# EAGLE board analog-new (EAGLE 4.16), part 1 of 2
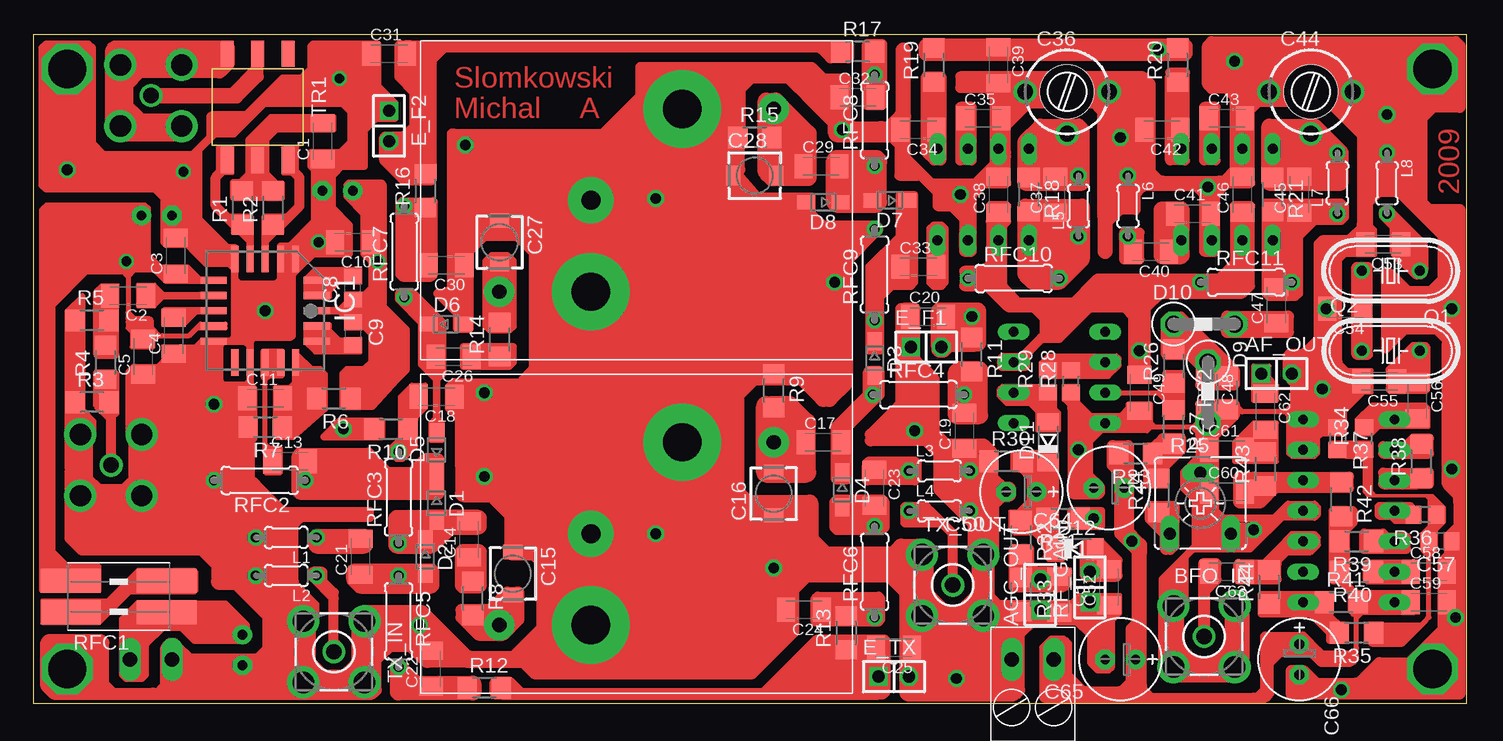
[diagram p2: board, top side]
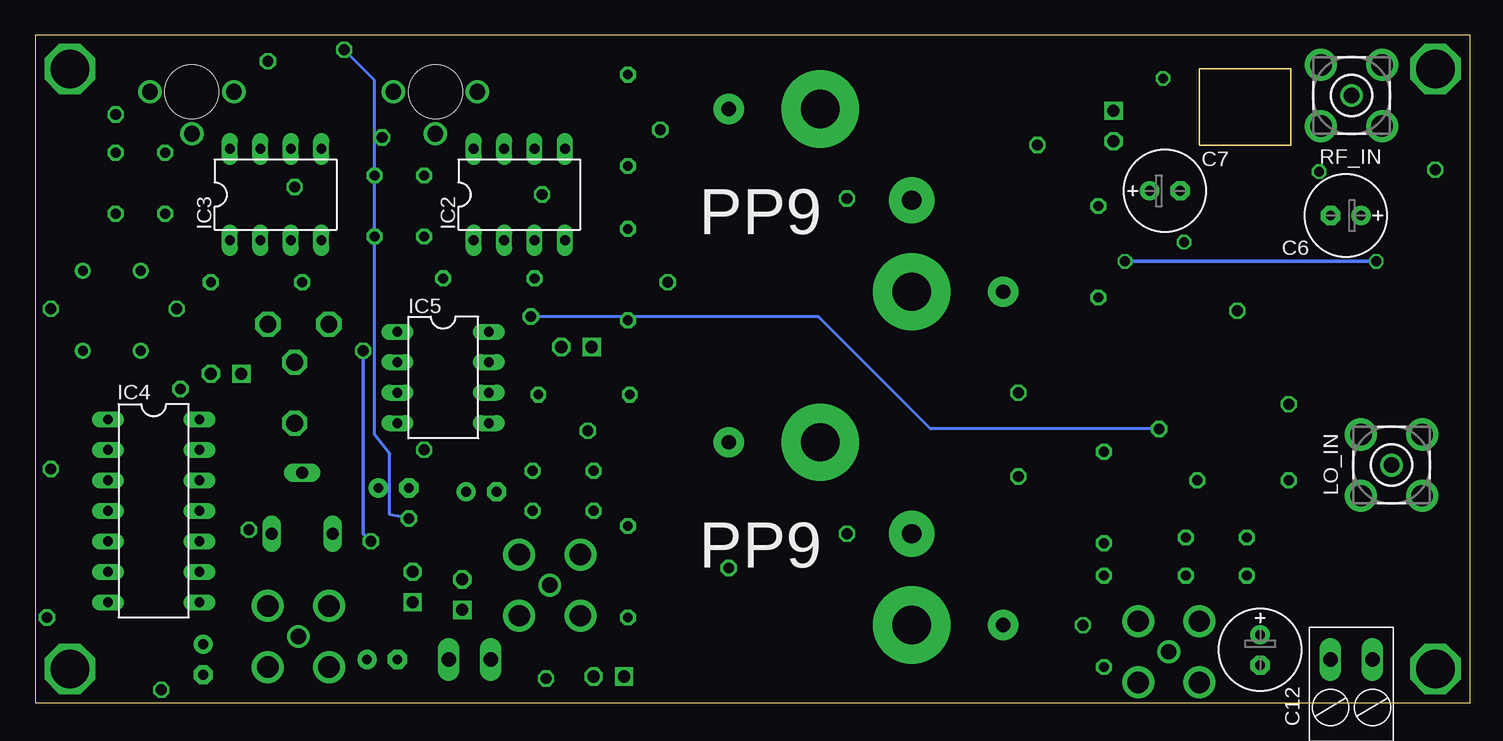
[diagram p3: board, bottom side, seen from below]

Size 119.52 x 55.71 mm. Coordinates in mm from the lower left corner, seen from the top.
Outline: 0,0 119.52,0 119.52,55.71 0,55.71 0,0
Copper layers (1*16): Top 0.035mm / dielectric 1.5mm / Bottom 0.035mm
Design rules "default": minimum track width 10mil, minimum drill 24mil, track to track 8mil, track to pad 8mil, pad to pad 8mil, via to via 8mil, smd to smd 8mil, copper to edge 40mil, drill to drill 8mil, minimum pad ring 10mil, minimum via ring 8mil, stop-mask expansion 4mil, vias tented up to drill 0mil, thermal gap 10mil

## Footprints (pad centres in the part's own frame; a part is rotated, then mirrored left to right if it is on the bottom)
RIACON-2 = drill 1.2 long: P$1 0,1.75; P$2 0,-1.75
1X02 = drill 1.016 square: 1 -1.27,0 | drill 1.016 octagon: 2 1.27,0
BU-SMA-V = drill 1.27 round: 1 0,0 | drill 1.778 round: 2 -2.55,2.55; 3 2.55,2.55; 4 2.55,-2.55; 5 -2.55,-2.55
C1206K = smd 1.5 x 2: 1 -1.5,0; 2 1.5,0
E2,5-7 = drill 0.813 pad 1.6 round: + -1.27,0 | drill 0.813 pad 1.6 octagon: - 1.27,0
C0805 = smd 1.3 x 1.5: 1 -0.95,0; 2 0.95,0
CTRIMTZBX4 = smd 1.6 x 1.2: 1 0,1.8; 2 0,-1.8
CTRIM3040.428 = drill 1.3 round: 1A -3.5,0; 1B 3.5,0; 2 0,-3.5 | hole 4.5: 0,0
SOD323-W = smd 1.5 x 1.2: A 1.45,0; C -1.45,0
C1702-05 = drill 1.397 octagon: A 2.54,0; C -2.54,0
SOD80C = smd 1.4 x 1.8: A 1.7,0; C -1.7,0
PP9 = drill 1.6 pad 3.81 round: GND 0,7.62 | drill 1.2 pad 2.54 round: IO1 7.62,0; IO2 -15.24,15.24 | drill 3.2 pad 6.452 round: P$1 0,0; P$2 -7.62,15.24
PLCC20S = smd 0.6 x 2.2: 1 0,4.3; 2 -1.27,4.3; 3 -2.54,4.3; 9 -2.54,-4.3; 10 -1.27,-4.3; 11 0,-4.3; 12 1.27,-4.3; 13 2.54,-4.3; 19 2.54,4.3; 20 1.27,4.3 | smd 2.2 x 0.6: 4 -4.3,2.54; 5 -4.3,1.27; 6 -4.3,0; 7 -4.3,-1.27; 8 -4.3,-2.54; 14 4.3,-2.54; 15 4.3,-1.27; 16 4.3,0; 17 4.3,1.27; 18 4.3,2.54
DIL08 = drill 0.813 long: 1 -3.81,-3.81; 2 -1.27,-3.81; 3 1.27,-3.81; 4 3.81,-3.81; 5 3.81,3.81; 6 1.27,3.81; 7 -1.27,3.81; 8 -3.81,3.81
DIL14 = drill 0.813 long: 1 -7.62,-3.81; 2 -5.08,-3.81; 3 -2.54,-3.81; 4 0,-3.81; 5 2.54,-3.81; 6 5.08,-3.81; 7 7.62,-3.81; 8 7.62,3.81; 9 5.08,3.81; 10 2.54,3.81; 11 0,3.81; 12 -2.54,3.81; 13 -5.08,3.81; 14 -7.62,3.81
0204/5 = drill 0.813 octagon: 1 -2.54,0; 2 2.54,0
HC49U70 = drill 0.813 round: 1 -2.413,0; 2 2.413,0
R1206 = smd 1.6 x 1.803: 1 -1.422,0; 2 1.422,0
CA6V = drill 1.016 long: A -2.54,-2.54; E 2.54,-2.54; S 0,2.54
R0805 = smd 1.3 x 1.5: 1 -0.95,0; 2 0.95,0
WE-CMS_7427521 = smd 5 x 2: 1 -4,1.3; 2 -4,-1.3; 3 4,-1.3; 4 4,1.3
0207/7 = drill 0.813 octagon: 1 -3.81,0; 2 3.81,0
MINICIRCUITS-W38 = smd 1.067 x 2.184: 1 -2.54,6.35; 2 0,6.35; 3 2.54,6.35; 4 2.54,-2.54; 5 0,-2.54; 6 -2.54,-2.54

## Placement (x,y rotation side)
+-5V  [RIACON-2]  9.84,3.64 90 bottom
+-5V1  [RIACON-2]  83.34,3.64 90 top
AF_OUT  [1X02]  103.66,27.46 0 top
AGC_OUT  [1X02]  83.97,9.04 90 top
BFO_IN  [BU-SMA-V]  97.63,5.55 0 top
C1  100n  [C1206K]  24.12,46.83 90 top
C2  100n  [C1206K]  7.93,33.97 180 top
C3  100n  [C1206K]  11.9,37.3 90 top
C4  100n  [C1206K]  11.74,30.63 90 top
C5  100n  [C1206K]  9.2,28.89 90 top
C6  100u  [E2,5-7]  10.31,40.63 180 bottom
C7  100u  [E2,5-7]  25.39,42.7 0 bottom
C8  1n  [C0805]  26.67,34.6 90 top
C9  1n  [C0805]  26.67,30.79 270 top
C10  100n  [C1206K]  26.67,38.41 180 top
C11  100n  [C1206K]  19.36,25.39 0 top
C12  100u  [E2,5-7]  17.46,4.44 270 bottom
C13  1n  [C1206K]  21.43,20.16 0 top
C14  1n  [C1206K]  36.35,13.65 90 top
C15  30p  [CTRIMTZBX4]  40,10.79 180 top
C16  30p  [CTRIMTZBX4]  61.75,17.46 0 top
C17  1n  [C1206K]  65.88,21.74 0 top
C18  100n  [C1206K]  33.65,25.55 180 top
C19  100n  [C1206K]  77.62,22.7 90 top
C20  100n  [C1206K]  74.61,32.22 0 top
C21  1n  [C1206K]  27.3,12.22 90 top
C22  100n  [C1206K]  33.17,2.85 90 top
C23  1n  [C1206K]  70.16,17.93 270 top
C24  100n  [C1206K]  64.29,7.77 180 top
C25  100n  [C1206K]  71.75,4.6 180 top
C26  1n  [C1206K]  35.08,28.89 180 top
C27  30p  [CTRIMTZBX4]  38.89,38.41 180 top
C28  30p  [CTRIMTZBX4]  60.16,43.97 270 top
C29  1n  [C1206K]  65.72,44.76 0 top
C30  100n  [C1206K]  34.44,36.51 180 top
C31  100n  [C1206K]  29.68,54.13 0 top
C32  100n  [C1206K]  68.73,50.48 0 top
C33  100p  [C1206K]  73.81,36.35 0 top
C34  10n  [C1206K]  73.81,47.78 180 top
C35  22n  [C1206K]  79.21,48.73 0 top
C36  30p  [CTRIM3040.428]  86.2,50.95 0 top
C37  100p  [C1206K]  85.24,42.38 90 top
C38  100n  [C1206K]  80.48,42.38 90 top
C39  10n  [C1206K]  80.48,53.17 270 top
C40  22n  [C1206K]  93.18,37.62 180 top
C41  100p  [C1206K]  96.67,40.79 0 top
C42  10n  [C1206K]  94.13,47.78 180 top
C43  22n  [C1206K]  99.53,48.73 0 top
C44  30p  [CTRIM3040.428]  106.52,50.95 0 top
C45  100p  [C1206K]  105.56,42.38 90 top
C46  100n  [C1206K]  100.8,42.38 90 top
C47  10p  [C1206K]  103.66,33.17 90 top
C48  10n  [C1206K]  97.94,25.87 270 top
C49  100n  [C1206K]  92.23,25.87 270 top
C50  47u  [E2,5-7]  82.39,17.61 180 top
C51  10n  [C1206K]  85.56,9.04 270 top
C52  10n  [C1206K]  89.69,9.68 90 top
C53  [C1206K]  112.55,38.25 180 top
C54  [C1206K]  109.37,32.85 180 top
C55  [C1206K]  112.23,26.82 180 top
C56  [C1206K]  115.41,25.23 270 top
C57  10n  [C0805]  117.31,13.49 180 top
C58  10n  [C1206K]  116.36,10.95 0 top
C59  100n  [C1206K]  116.36,8.41 0 top
C60  10n  [C1206K]  99.53,17.61 0 top
C61  10n  [C1206K]  99.53,21.11 0 top
C62  10n  [C1206K]  102.71,24.28 270 top
C63  10n  [C1206K]  99.53,10.95 180 top
C64  100u  [E2,5-7]  89.69,17.93 180 top
C65  100u  [E2,5-7]  90.64,3.64 180 top
C66  100u  [E2,5-7]  105.56,3.64 270 top
D1  [SOD323-W]  33.65,16.66 270 top
D2  [SOD323-W]  32.7,12.22 270 top
D3  [SOD323-W]  70.16,28.73 270 top
D4  [SOD323-W]  67.46,17.77 270 top
D5  [SOD323-W]  33.65,21.11 90 top
D6  [SOD323-W]  34.44,31.59 0 top
D7  [SOD323-W]  71.43,41.9 180 top
D8  [SOD323-W]  65.88,41.74 180 top
D9  [C1702-05]  97.94,25.87 270 top
D10  [C1702-05]  97.63,31.58 0 top
D11  [SOD80C]  84.61,21.74 90 top
D12  [SOD80C]  86.83,12.85 0 top
E_F1  [1X02]  74.45,29.68 0 top
E_F2  [1X02]  29.68,48.09 270 top
E_TX  [1X02]  71.75,2.22 0 top
F1  PP9  [PP9]  46.51,34.28 0 bottom
F2  PP9  [PP9]  46.51,6.5 0 bottom
IC1  AD831  [PLCC20S]  19.36,32.7 270 top
IC2  MC1350  [DIL08]  79.21,42.38 0 bottom
IC3  MC1350  [DIL08]  99.53,42.38 0 bottom
IC4  MC1496  [DIL14]  109.69,16.03 270 bottom
IC5  CA3130N  [DIL08]  85.56,27.14 270 bottom
L1  [0204/5]  21.11,13.8 180 top
L2  [0204/5]  21.11,10.63 180 top
L3  [0204/5]  75.56,19.36 0 top
L4  [0204/5]  75.56,16.03 0 top
L5  [0204/5]  87.15,41.43 90 top
L6  [0204/5]  91.28,41.43 270 top
L7  [0204/5]  108.74,43.33 90 top
L8  [0204/5]  112.87,43.33 270 top
LO_IN  [BU-SMA-V]  6.5,19.84 90 bottom
Q1  [HC49U70]  113.18,36.03 180 top
Q2  [HC49U70]  113.18,29.36 0 top
R1  100  [R1206]  17.46,41.27 90 top
R2  100  [R1206]  20,41.27 90 top
R3  100  [R1206]  4.92,25.08 0 top
R4  [R1206]  6.03,28.41 90 top
R5  100  [R1206]  4.92,31.9 0 top
R6  4k7  [R1206]  25.08,25.39 180 top
R7  4k7  [R1206]  19.36,23.01 180 top
R8  470  [R1206]  36.67,8.72 270 top
R9  560  [R1206]  61.75,26.03 270 top
R10  1k  [R1206]  29.84,22.85 180 top
R11  1k  [R1206]  78.26,29.04 270 top
R12  2k2  [R1206]  37.62,1.26 0 top
R13  2k2  [R1206]  67.78,5.87 90 top
R14  [R1206]  38.89,30.32 90 top
R15  [R1206]  60.16,47.14 0 top
R16  1k  [R1206]  32.7,42.7 90 top
R17  1k  [R1206]  68.73,54.29 0 top
R18  1k  [R1206]  83.02,42.38 270 top
R19  5k1  [R1206]  75.08,53.17 90 top
R20  10k  [R1206]  95.4,53.17 90 top
R21  2k2  [R1206]  103.34,42.38 270 top
R22  100k  [R1206]  99.53,25.87 90 top
R23  10k  [R1206]  91.91,20.79 180 top
R24  100  [R1206]  93.82,17.3 90 top
R25  22k  [CA6V]  97.31,16.66 0 top
R26  1M  [R1206]  95.09,28.09 90 top
R27  1M  [R1206]  95.09,23.01 270 top
R28  3k3  [R0805]  86.51,26.82 90 top
R29  10k  [R0805]  84.61,26.82 90 top
R30  47k  [R1206]  81.12,20.15 0 top
R31  220  [R1206]  85.88,15.39 180 top
R32  [R1206]  82.39,13.81 270 top
R33  [R1206]  82.39,9.04 270 top
R34  1k  [R0805]  110.96,22.06 90 top
R35  820  [R1206]  110.33,5.87 180 top
R36  1k  [R0805]  116.04,15.71 180 top
R37  1k  [R0805]  108.74,22.06 270 top
R38  100  [R1206]  115.72,20.15 90 top
R39  10k  [R1206]  110.33,13.49 180 top
R40  3k3  [R1206]  110.33,10.95 180 top
R41  1k3  [R1206]  109.06,8.41 0 top
R42  3k3  [R1206]  109.06,16.98 270 top
R43  1k  [R1206]  102.71,19.52 90 top
R44  50  [R1206]  103.02,9.68 90 top
RF_GAIN  [1X02]  88.1,9.68 90 top
RF_IN  [BU-SMA-V]  9.84,50.64 180 bottom
RFC1  [WE-CMS_7427521]  7.14,8.88 0 top
RFC2  [0207/7]  18.89,18.57 180 top
RFC3  [0207/7]  30.48,17.14 90 top
RFC4  [0207/7]  73.81,25.71 0 top
RFC5  [0207/7]  30.48,6.82 270 top
RFC6  [0207/7]  70.16,10.95 90 top
RFC7  [0207/7]  30.95,37.62 90 top
RFC8  [0207/7]  70.16,48.57 90 top
RFC9  [0207/7]  70.16,35.71 90 top
RFC10  [0207/7]  81.75,35.39 0 top
RFC11  [0207/7]  101.12,35.08 0 top
TR1  [MINICIRCUITS-W38]  18.73,51.59 180 top
TX_IN  [BU-SMA-V]  25.08,4.28 270 top
TX_OUT  [BU-SMA-V]  76.67,9.84 0 top

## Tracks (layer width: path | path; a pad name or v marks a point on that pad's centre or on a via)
C62
  Top 1.27: 102.71,21.11 C62.2 | 102.71,21.11 102.87,20.94 R43.2 | C61.2 102.71,21.11
N$1
  Top 0.61: 9.2,33.97 C2.1 IC1.10
N$2
  Top 1.422: R8.1 36.2,10.15 36.19,10.15 36.35,10.31 C14.1
N$3
  Top 0.813: R3.2 6.35,24.92 6.5,24.76 LO_IN.1
  Top 1.422: R4.1 6.34,26.67 R3.2
N$4
  Top 1.016: TR1.4 16.19,53.49 15.87,53.17 13.49,53.17 13.48,53.19 RF_IN.4
  Top 2.184: 7.3,53.17 8.24,53.19 RF_IN.5 | RF_IN.4 8.26,53.19 7.3,53.17 | RF_IN.3 8.26,48.09 7.3,48.09 | 7.3,48.09 8.24,48.09 RF_IN.2 | 7.3,48.09 7.3,53.17
N$5
  Top 0.61: IC1.20 23.66,30.3 23.81,30.16 | C9.2 25.08,29.84 24.76,30.16 23.81,30.16 | IC1.19 23.81,30.16
N$6
  Top 0.61: IC1.2 23.66,35.09 23.81,35.24 | C8.2 25.08,35.55 24.76,35.24 23.81,35.24 | 23.81,35.24 IC1.3
N$7
  Top 1.422: C2.2 6.43,31.83 6.35,31.74 6.34,31.75 R5.2 6.03,31.58 R4.2
N$8
  Top 1.422: R14.1 C26.1
N$9
  Top 1.27: 34.76,15.15 34.76,15.23 34.74,15.21 D1.A
  Top 1.422: 33.17,13.33 | 33.17,13.33 33.17,13.65 | RFC3.1 33.17,13.33 | 33.17,13.33 | 33.17,13.65 D2.C | C14.2 34.76,15.15 34.67,15.15 33.17,13.65
N$10
  Top 0.61: 8.89,8.25 16.03,8.25 17.78,6.5 17.78,5.55 17.46,5.23 13.49,5.23 12.54,6.18 | 12.54,6.18 | 12.54,6.18 12.38,6.34 10.79,6.34 9.36,4.92 9.36,2.38 9.04,2.06 7.77,2.06 | 7.46,6.03 7.46,2.38 7.77,2.06 | 7.46,6.03 7.46,6.18 | 7.77,2.06 7.93,2.06 | 7.46,6.03 7.46,6.98 8.73,8.25
N$11
  Top 0.61: R2.1 20,40.32 19.36,40.32 19.36,39.84 | IC1.6 19.36,39.84 | 19.36,39.84 19.36,40.48 21.11,40.48
  Top 0.813: TR1.1 21.27,44.76 22.22,43.81 22.22,41.43 20.63,39.84 20,40 R2.1
N$12
  Top 0.61: RFC1.3 11.14,7.49 9.36,5.71 8.09,5.71
  Top 1.27: C12.+ 14.44,5.71 12.7,7.46 11.43,7.46 11.27,7.61 11.24,7.58 RFC1.3
  Top 1.778: 11.11,7.61 RFC1.3 | +-5V.P$2 8.09,5.71
N$13
  Top 0.813: TR1.5 18.73,53.02 16.35,50.63 | RF_IN.1 16.35,50.63 | 16.35,50.63
N$14  (via drill 3.2)
  Top 0.305: v116.68,2.85 116.84,2.85 117.31,2.38 | 117.31,2.38 117.95,1.74 117.31,1.74 115.72,3.33 116.36,3.33 117.31,2.38
  Top 1.676: 117.31,2.38 116.36,1.42
N$15
  Top 1.016: 21.59,23.49 23.17,25.08
N$16
  Top 1.016: 25.71,37.94 25.71,38.89
N$17
  Top 0.406: C13.1 19.84,20.31 19.36,20.79 19.36,20.95 | 19.36,20.95 19.36,21.58 | 19.36,21.58 19.36,26.98 | 19.36,26.98 19.36,27.3 | 19.36,27.62 IC1.16 | 19.36,26.98 19.68,27.3 20.79,27.3 20.79,29.36 19.2,29.36 19.2,27.14 19.36,26.98 | 19.36,20.95 19.36,19.2 20.63,19.2 20.63,21.27 19.68,21.27 19.36,21.58
  Top 0.61: IC1.17 20.49,28.4 20.47,28.41 20.46,28.4 IC1.16 | 19.36,27.3 19.36,27.62
N$18
  Top 0.406: 6.66,23.81 6.98,24.12 6.98,27.46 6.82,27.62 5.23,27.62 5.23,26.98 | 5.23,26.98 5.23,27.14 | 5.23,26.98 5.23,24.76 6.35,23.65
N$19
  Top 0.406: 5.55,24.76 5.55,26.19
N$20
  Top 0.406: 5.39,28.89 5.23,29.04 5.23,34.28 5.71,34.76 6.98,34.76 6.98,29.04 6.82,28.89 5.39,28.89
N$21
  Top 0.406: 6.66,30.47 6.66,31.11
N$22
  Top 0.406: 5.55,32.06 5.55,34.44
N$23
  Top 1.016: 40.48,9.2 40.48,6.98 39.21,5.71 37.14,5.71 35.71,7.14 35.71,7.77 38.1,7.77 39.52,9.2 40.32,9.2
N$24
  Top 1.016: 39.84,6.98 39.84,7.93
N$25
  Top 1.422: F2.IO1 | F2.IO1 | C15.1 38.89,7.88 38.89,7.3 | 38.89,7.3 F2.IO1 | R8.2 36.36,7.3 38.89,7.3
N$26
  Top 1.676: 61.75,24.44 R9.2 | F2.IO2 61.75,24.44 | 61.75,24.44 | F2.IO2 | F2.IO2 C17.1 | F2.IO2 | 61.75,21.58 | 61.75,21.58 F2.IO2 | C16.1 61.75,21.58
N$27
  Top 1.016: 69.69,25.87 69.69,27.62 70.48,27.62 70.48,25.71 67.78,23.01 67.78,18.73 | 69.69,25.39 69.69,25.87 | 69.69,25.87 69.69,25.71 66.99,23.01 66.99,18.73 67.62,18.73
  Top 1.27: D3.A 70.16,25.87 RFC4.1 69.69,25.39 67.38,23.08 C17.2 67.46,21.74 D4.C
N$28
  Top 1.422: R11.2 78.26,26.35 RFC4.2 C19.2
N$29
  Top 1.422: C18.2 32.06,25.55 31.27,24.76 R10.1 | RFC3.2 | RFC3.2 31.27,21.74 R10.1 | R10.1
N$30
  Top 1.016: 36.98,6.34 38.89,6.34
N$31  (via drill 0.9)
  Top 1.27: R11.1 77,30.47 76.67,30.79 | 76.67,30.79 76.04,31.43 76.04,32.22 | 76.04,32.22 | 76.04,32.22 C20.2 | E_F1.2 75.72,29.84 76.67,30.79 | E_F1.2 | v78.26,32.22 E_F1.2 | R10.2 | R10.2 | v25.87,22.85 R10.2
  Bottom 0.254: v78.26,32.22 54.29,32.22 44.92,22.85 v25.87,22.85
N$32
  Top 1.422: 26.98,10.63 27.07,10.72 C21.1 | 26.98,10.63 RFC5.1 33.17,10.63 | 26.98,10.63 | 33.17,10.63 | 33.17,10.63 D2.A | 33.17,10.63 32.86,10.63
N$33  (via drill 3.2)
  other vias: 2.85,52.86
N$34
  Top 1.27: D4.A 70.14,16.32 70.16,16.34 | 70.16,16.34 | 70.16,16.34 C23.2 | RFC6.2 70.16,16.34
N$35
  Top 1.27: C24.1 67.31,7.77 R13.2 67.78,7.14 | 67.78,7.14 RFC6.1 | 67.78,7.14
N$36
  Top 1.016: R12.2 39.05,0.79 | 70.48,2.38 E_TX.1 70.48,0.79 39.05,0.79 | 39.05,0.79 38.57,0.79 38.57,1.74 39.68,1.74 40.48,0.95
  Top 1.27: 70.16,4.6 | 70.16,4.6 C25.2 70.25,4.53 70.16,4.44 70.16,4.45 R13.1 | 70.48,2.38 70.48,4.28 70.16,4.6
N$37
  Top 1.422: 30.48,2.06 RFC5.2 | RFC5.2 | 30.48,2.06 31.11,1.42 32.86,1.42 32.93,1.35 C22.1 33.26,1.35 33.33,1.42 R12.1 | RFC5.2 31.9,1.58 | 30.48,2.06 30.48,0.95 36.67,0.95 36.67,1.58 31.59,1.58
N$38
  Top 0.61: 18.09,39.2 18.09,40.16 17.62,40 | 18.09,39.2 IC1.7 | 18.09,39.2 18.09,40.48 16.51,40.48
  Top 0.813: TR1.3 16.19,44.76 15.24,43.81 15.24,41.43 16.82,39.84 17.62,40 R1.1
N$39
  Top 1.422: 27.14,13.81 27.23,13.72 C21.2 | L1.1 27.14,13.81 | 27.14,13.81
N$40
  Top 0.813: L2.1 25.08,9.2 TX_IN.1
N$41
  Top 1.27: 70.16,19.36 | C23.1 70.16,19.36 | 70.16,19.36 L3.1 | 70.16,19.36
N$42
  Top 0.813: TX_OUT.1 76.67,14.12 75.08,15.71 | 75.08,15.71 74.77,16.03 L4.1 | L4.1 | 75.08,15.71 74.45,16.34 72.7,16.34 72.7,15.08 75.56,15.08
N$43
  Top 1.422: 37.14,9.84 35.87,9.84 35.87,12.54 37.14,12.54 37.14,9.84
N$44
  Top 1.016: 33.17,18.57 33.17,18.73 33.15,18.7 33.15,18.41 | 33.15,18.41 D1.C | 33.15,18.41 33.17,18.41 | 33.65,18.88 D5.C
  Top 1.27: 33.65,18.25 | D1.C 33.65,18.25 | 33.65,18.25 33.65,18.88 | 33.65,18.25
  Top 1.422: C13.2 22.77,20.24 22.86,20.15 22.7,20 RFC2.1 33.17,18.57
N$45
  Top 0.61: 33.65,29.04 33.58,28.97 | D5.A 33.65,29.04 | 33.65,29.04
  Top 1.422: C26.2 33.58,28.97 33.65,29.04 32.99,29.7 D6.C 32.99,32.04 33.02,32.06 31.27,33.81 RFC7.1
N$46
  Top 1.676: R14.2 F1.IO1 | F1.IO1 | F1.IO1 C27.1
N$47
  Top 1.676: 70,44.76 C29.2 | 70,44.76 RFC8.1 | 70,44.76 69.98,44.74 D7.A 70,42.22 | 70,42.22 | D8.C 69.53,41.74 70,42.22
N$48
  Top 1.422: 33.02,15.39 37.14,15.39 37.14,14.76 34.76,14.76 33.17,13.17 30.32,13.17 30.32,15.39 33.49,15.39 33.65,15.23
N$49
  Top 1.676: F1.IO2 61.75,47.14 61.59,46.98 61.58,46.99 R15.2 61.91,47.14 61.96,47.09 61.96,44.76 | C28.1 61.96,44.76 | 61.96,44.76 C29.1
N$51
  Top 1.27: D7.C 72.88,38.91 70.64,36.66 | 70.64,36.66 70.16,36.19 RFC9.1 | RFC9.1 | D3.C RFC9.1 | C33.1 70.96,36.35 70.64,36.66
N$52
  Top 0.61: 29.21,43.17 29.21,33.01 31.11,31.11 31.11,27.77 30.32,26.98 28.25,24.76 25.87,24.76 25.87,27.46 26.19,27.77 27.62,27.77 28.25,28.41
N$53
  Top 1.422: C32.2 70.23,50.39 70.16,50.32 RFC8.2 R17.2
N$54
  Top 1.016: R17.1 67.31,54.6 67.31,54.76 65.88,54.76 | C31.2 31.18,54.69 31.11,54.76 31.43,54.76 | 31.43,54.76 32.7,54.76 | 32.7,54.76 65.88,54.76 | 32.7,54.76 32.7,54.6 32.7,46.82 | 32.7,46.82 R16.2 | 32.7,46.82 | 32.7,46.82 E_F2.2 | 32.7,46.82 | 31.43,54.76 30.63,54.76 30.63,52.22 31.9,50.95 31.9,48.09 30.95,47.14 29.36,47.14 29.36,45.24 30.95,43.65 33.17,43.65 33.17,53.65 33.97,54.45 | 65.88,54.76 67.94,54.76 67.94,53.81 66.51,53.81 65.72,54.6
N$55
  Top 0.813: 18.73,42.86 TR1.2 | R1.2 17.46,42.86 18.73,42.86 | R2.2 18.88,43.01 18.73,42.86
  Top 1.016: C1.2 19.91,48.32 18.73,47.14 TR1.2
N$56
  Top 1.422: 30.95,14.44 33.17,14.44
N$57
  Top 1.422: 26.82,10.95 33.17,10.95
N$58
  Top 1.422: 26.82,10.31 26.82,10.79 | 26.82,10.31 | 26.82,10.31 27.3,9.84 33.17,9.84 33.17,10.47
N$59
  Top 1.422: 27.62,13.17 23.65,13.17 23.65,13.81 27.62,13.81 27.62,13.49
N$60
  Top 0.813: 25.08,8.73 23.33,10.47 23.33,10.95 24.13,10.95 24.13,10.15
N$61
  Top 0.61: C4.2 11.74,32.38 12.06,32.7 IC1.11
N$62  (via drill 3.2)
  other vias: 116.68,52.86
N$63
  Top 0.61: 21.9,25.39 21.9,27.93 | 21.9,27.93 IC1.18 | 21.9,25.39 C11.2 20.79,25.39 20.63,25.23 20.78,25.08 R7.1 | 21.9,25.39 R6.2 | 21.9,27.93 21.9,26.66 21.43,26.19
N$64
  Top 0.406: 19.52,47.62 19.52,44.13 20.32,43.33 20.79,43.33 20.79,42.06 16.66,42.06 16.66,43.49 17.3,43.49 17.93,44.13 17.93,46.98 19.84,48.89 25.08,48.89 25.08,47.78
N$65
  Top 0.61: 25.08,5.23 25.55,4.76 | 25.08,5.23 | 24.6,4.76 25.08,5.23
N$66
  Top 0.305: 9.68,37.46 9.68,41.27 9.36,41.59 1.11,41.59 0.79,41.27 0.63,41.11 0.63,40.79 0.63,40.63 0.63,9.36
N$67
  Top 0.406: 25.08,47.78 20.32,47.78 19.36,46.82 19.36,44.13
N$68
  Top 0.406: 18.25,43.97 18.25,46.98
N$69
  Top 1.016: 19.52,43.49 18.89,44.13
N$70
  Top 1.016: 17.62,43.33 18.57,44.28
N$71
  Top 1.016: 17.93,42.38 19.36,42.38
N$73
  Top 0.305: 25.4,35.08 27.3,35.08 27.3,36.19 23.49,36.19 22.7,35.39 22.7,33.81 24.76,33.81 24.76,34.28 25.55,35.08
N$74
  Top 0.813: 26.03,35.87 23.65,35.87 23.33,35.55
N$75
  Top 0.813: 26.98,35.39 25.24,35.39 24.28,34.44
N$76
  Top 0.813: 24.44,34.92 23.17,34.92 23.17,34.44
N$77
  Top 0.305: 23.33,29.36 22.7,30 22.7,31.58 24.76,31.58 24.76,31.11 25.55,30.31 27.3,30.31 27.3,29.2 23.49,29.2 23.33,29.36 | 23.33,29.36
N$78
  Top 0.813: 26.51,29.52 23.65,29.52 23.33,29.84
N$79
  Top 0.813: 26.35,30 25.4,30 24.44,30.95
N$80
  Top 0.813: 24.13,30.47 24.13,30.95
N$81
  Top 0.813: 23.01,30.47 23.01,31.11
N$83
  Top 1.016: RFC1.4 8.44,10.18 5.87,7.61 3.17,7.61 RFC1.2
N$84
  Top 0.61: 28.25,34.6 28.25,36.82 27.62,37.46 27.62,40.79 26.19,42.22 26.19,43.17 26.35,43.33 29.05,43.33 29.21,43.17
N$85
  Top 1.676: 61.59,24.76 63.02,24.76 64.45,23.33 64.45,19.2 62.38,19.2 61.11,19.2 61.11,24.76
N$86
  Top 1.422: 26.67,25.87 27.94,27.14
N$87
  Top 1.422: 26.35,26.66 26.82,27.14
N$88
  Top 1.422: 27.14,42.7 28.73,42.7 28.73,41.59
N$89
  Top 1.422: 28.09,37.62 28.09,39.68
N$90
  Top 1.422: 28.73,31.58 28.73,33.97
N$91
  Top 1.422: 26.98,32.85 28.25,32.85
N$92
  Top 0.61: 26.35,33.49 | 26.35,33.49 25.55,32.7 26.35,31.9
N$93
  Top 0.305: 21.43,26.35 20.16,26.35 20.16,22.22 20.32,22.06 21.74,22.06 24.44,24.44 | 24.44,24.44 23.49,24.28 23.65,24.44 24.44,24.44 | 24.44,24.44 24.44,27.46 23.97,27.93 23.01,27.93 21.9,29.04
  Top 0.61: 21.9,29.04 23.17,27.77
N$94
  Top 0.813: 22.22,25.71 22.22,28.25
N$95
  Top 0.813: 22.7,25.87 22.7,27.77
N$96
  Top 0.813: 23.97,26.19 23.97,27.3
N$97
  Top 0.813: 23.65,26.19 23.65,27.62
N$98
  Top 0.813: 23.17,26.5 23.17,27.46
N$99
  Top 1.016: 23.49,25.08 23.81,24.6 21.43,22.54
N$100
  Top 1.016: 20.63,23.65 20.63,24.76
N$101
  Top 1.016: 21.11,23.81 22.38,25.08
N$102
  Top 1.016: 21.74,24.76 21.74,25.39
N$103
  Top 0.305: 13.49,11.11 13.65,10.95 13.65,9.36 13.49,9.2 8.09,9.2 5.55,6.66 0.79,6.66 0.79,6.82 0.79,8.57 6.19,8.57 8.73,11.11 13.49,11.11
N$104
  Top 1.27: 12.38,52.7 15.55,52.7 16.19,53.33 16.19,54.6 6.82,54.6 6.66,54.45 6.66,53.17 | 12.38,47.46 7.3,47.46 6.66,48.09 6.66,53.17 | 6.66,53.17 7.3,53.81
N$105
  Top 1.27: 12.85,53.97 15.55,53.97
N$106
  Top 1.016: 18.73,54.6 18.73,52.22 16.98,50.48 9.84,50.48
N$107
  Top 1.016: 16.82,50.79 9.84,50.79 9.84,50.63
N$108
  Top 0.61: 8.57,10.63 8.89,10.63
N$109
  Top 0.61: 8.25,9.52 8.89,9.52
N$110
  Top 0.61: 5.87,8.25 5.55,8.25
N$111
  Top 0.61: 5.71,7.14 5.55,7.14
N$112
  Top 0.305: 0.79,9.36 5.55,9.36 5.55,11.42 5.39,11.58 2.85,11.58 1.74,12.69
N$113
  Top 0.61: 5.39,11.27 2.69,11.27 1.74,12.22
N$114
  Top 0.305: 20.79,39.84 20.79,39.2 20.32,39.2 19.52,38.41
N$115
  Top 1.016: 23.97,2.53 23.17,3.33
N$116
  Top 0.61: 13.49,8.25 17.78,6.03
N$117
  Top 0.61: 7.93,6.82 8.57,7.46
N$118
  Top 1.422: 8.09,2.69 8.73,2.69 8.73,5.23 10.16,6.66
N$119
  Top 1.422: 10.63,6.98 12.54,6.98 13.65,5.87
N$121
  Top 1.422: 7.93,5.87 8.73,6.66
N$122
  Top 1.016: 24.6,40.79 24.6,43.17
N$123
  Top 1.422: 24.92,40.48 25.87,39.52
N$124
  Top 1.422: 24.28,39.84 24.28,39.52 24.28,38.89
  Top 1.778: 24.28,39.52 24.28,44.92
N$125
  Top 1.422: 24.92,39.05 24.92,38.73
N$126
  Top 1.422: 23.65,39.2 23.01,38.57
N$127
  Top 1.422: 25.08,37.94 22.06,37.94 21.74,37.62
N$128
  Top 1.422: 22.54,37.46 22.22,37.14
N$129
  Top 1.422: 21.11,34.92 21.11,37.62
N$130
  Top 0.254: 17.62,30.16 17.62,30 17.93,29.68
N$131
  Top 0.254: 16.35,30.31 16.66,30.63
N$132
  Top 0.305: 10.95,32.85 16.03,32.85 16.03,32.54 13.65,32.54 12.7,31.58 10.79,31.58 | 10.79,31.58 10.95,32.85 | 10.95,32.85 10.79,32.7 10.79,31.58
N$133
  Top 0.813: 12.54,31.9 13.17,32.54
N$134
  Top 0.254: 8.73,34.92 8.89,34.76 | 8.73,34.92 10.16,34.92 | 10.16,34.92 | 10.16,34.92 10.95,34.12 | 8.73,34.92 8.73,33.01 10.16,33.01 10.95,33.81
N$135
  Top 0.61: 10.47,34.12 10,34.6
N$136
  Top 0.61: 10.16,33.33 10.63,33.81
N$137
  Top 0.305: 16.66,39.68 16.66,39.2 17.14,39.2 17.93,38.41
N$138
  Top 0.61: 17.93,38.89 17.62,39.2
N$139
  Top 0.61: 19.68,39.05 19.84,39.2
N$141
  Top 1.016: 25.71,2.06 26.98,3.33
N$142
  Top 1.016: 22.22,20.79 22.06,20.63 22.06,18.57 22.54,18.09
N$143
  Top 1.016: 22.06,18.57 22.06,17.61 22.22,17.46 33.81,17.46 33.81,20.31 32.7,20.31 31.27,18.88
N$144
  Top 1.016: 33.02,19.52 32.86,19.52 32.54,19.2
N$145
  Top 1.016: 22.22,20.79 27.94,20.79 29.84,18.88
N$146
  Top 1.422: RFC7.2 32.54,41.43 32.7,41.27 R16.1 32.85,41.28 32.94,41.18 C30.2
N$147
  Top 0.406: 31.9,23.65 31.9,21.42 30.79,20.31 30.32,20.31 29.84,20.79 29.84,21.27 30.63,22.06 30.63,25.55 31.59,26.5 32.7,26.5 32.7,24.6 31.9,23.81
N$148
  Top 0.406: 30.79,25.39 31.43,26.03
N$149
  Top 0.406: 31.75,23.96 32.38,24.6
N$150
  Top 0.406: 33.49,23.65 33.17,23.33 33.17,21.9 34.13,21.9 34.13,23.33 33.81,23.65
N$151
  Top 0.813: 33.17,35.55 33.33,35.71 33.33,41.74 30.79,41.74 30.63,41.59 30.63,35.71 30.79,35.55 33.17,35.55
N$152
  Top 0.61: 32.54,31.58 | 32.54,31.58 30.48,33.65 30.48,34.12 30.63,34.28 31.59,34.28 34.13,31.74 34.13,27.46 33.81,27.14 33.49,27.14 33.17,27.46 | 33.17,27.46 | 33.17,27.46 32.38,28.25 32.38,32.22
N$153
  Top 0.61: 33.81,29.84 33.81,31.9
N$154
  Top 0.61: 32.7,29.04 32.7,28.57 33.49,27.77
N$155
  Top 0.406: 8.25,22.85 8.25,27.62
N$157
  Top 0.61: 39.05,37.3 39.52,37.3 40,36.82 40,31.43 39.68,31.11 38.1,31.11 37.94,31.27 37.78,31.43 37.78,36.82 38.25,37.3 38.89,37.3
N$158
  Top 0.61: 36.03,29.68 40,29.68 40,28.41 39.68,28.09 35.87,28.09 35.87,29.68
N$159
  Top 0.406: 23.65,6.82 23.65,8.25 21.74,10.15
  Top 0.813: 21.9,15.08 22.38,15.55 | 21.9,15.08 | 23.17,7.3 23.17,7.46 21.74,8.88 21.74,10.15 21.74,14.92 21.9,15.08
N$160
  Top 0.406: 13.65,31.27 13.97,31.58 16.03,31.58 16.03,31.27 13.65,31.27
N$161
  Top 0.406: 12.38,29.68 12.22,29.68 | 12.38,29.68 13.65,29.68 | 10.95,29.68 12.38,29.68
N$162
  Top 0.406: 10.95,28.57 10.31,27.93 10.47,28.09 8.41,28.09 7.93,27.62 7.93,22.38 8.09,22.22
N$163
  Top 1.016: 8.89,48.73 7.62,50
N$164
  Top 1.016: 7.46,51.11 9.36,53.02
N$165
  Top 1.016: 8.89,19.2 8.89,19.04 7.62,17.77
N$166
  Top 1.016: 5.55,17.61 4.28,18.88
N$167
  Top 0.406: 2.85,19.52 2.85,32.7 4.12,33.97 4.12,24.44 5.08,23.49 5.08,22.38 4.76,22.06
N$168
  Top 0.406: 2.85,17.93 2.85,19.36 | 2.85,17.93 2.85,17.77 | 2.85,17.93 2.85,13.65 3.96,12.54 13.97,12.54
N$169
  Top 0.61: 3.81,33.17 3.17,32.54
N$170
  Top 0.61: 3.81,32.85 3.81,32.7
N$171
  Top 0.61: 4.12,23.96 | 4.12,23.96 4.92,23.17
N$172
  Top 0.305: 6.66,20.95 6.66,20.79 7.14,20.31
N$173
  Top 0.305: 6.35,20.95 6.35,20.79 5.87,20.31
N$178  (via drill 0.8)
  Top 0.305: 28.64,36.51 28.73,36.51 v28.73,36.82
  Top 0.406: 10.47,30.63 10.79,30.63 | 10.47,30.63 9.84,31.27 9.84,31.9 9.68,32.06 8.41,32.06 7.93,32.54 | IC1.12 13.81,31.43 13.01,30.63 9.36,30.63 9.2,30.47 | 8.25,36.19 7.93,35.87 7.93,35.55 | 8.25,31.43 | 7.93,35.55 7.93,32.54 | 7.93,32.54 7.93,32.06 | 7.93,32.06 7.93,31.74 8.25,31.43 | 7.93,35.55 8.57,36.19 | 7.93,35.55 | 7.93,35.55 7.46,36.03 | 7.93,32.06 7.93,31.27 8.25,30.95 8.25,29.68 10,29.68 10,30.16 10.47,30.63
  Top 0.61: 26.67,32.7 IC1.1 | 26.67,32.7 C9.1 | C8.1 26.67,32.7 | 9.04,36.19 8.25,36.19 | 9.04,36.19 11.74,36.19 C3.1 11.74,35.55 12.06,35.24 IC1.9 | C5.2 9.2,30.47 8.25,31.43 | 9.04,36.19 | C6.+ 9.04,36.19
  Top 0.813: 9.04,41.11 9.04,36.35 8.25,36.35 v7.77,36.82
  Top 1.016: 9.04,41.11 C6.+ | C10.1 28.64,38.5 28.57,38.57 28.57,40.16
  Top 1.27: C10.1 28.64,36.51 28.64,34.51 27.78,33.65 26.82,33.65 C8.1 | R6.1 27.14,25.39 28.57,26.82 28.57,30.95 27.78,31.74 26.82,31.74 C9.1 | RFC1.1 1.71,10.98 1.27,11.58 1.27,11.11 1.27,10.15 1.27,33.33 4.28,36.35 7.77,36.35 v7.77,36.82
  Top 1.422: 28.57,40.16 28.57,40.79 C7.+
  Bottom 0.305: v7.77,36.82 v28.73,36.82
N$179
  Top 0.61: 8.09,31.9 9.52,31.9
N$180
  Top 0.813: 9.52,31.43 8.73,31.43
N$181
  Top 0.61: 12.22,35.24 11.11,35.24 10.16,36.19
N$182
  Top 0.406: 15.08,35.24 13.97,35.24 12.85,36.35 10.63,36.35 9.36,37.62
N$183
  Top 0.61: 9.36,40.79 9.36,37.14 10,36.51
N$184
  Top 0.61: 9.2,36.51 9.68,36.51
N$185
  Top 0.61: 13.01,35.87 13.33,35.55 12.85,35.55
N$186
  Top 1.016: 1.11,33.81 1.11,40.95
N$187
  Top 1.676: 1.42,34.76 2.69,36.03
N$188
  Top 0.254: 21.43,44.13 20.79,44.13 20.79,46.35 21.59,46.35 | 21.59,46.35 21.74,46.35 21.74,44.6 | 21.59,46.35 22.06,46.35 22.06,44.13
N$189
  Top 0.254: 16.03,44.13 16.66,44.13 16.66,46.35 15.39,46.35 15.39,44.28
N$190
  Top 0.254: 21.9,44.6 21.9,46.19
N$191
  Top 0.254: 15.55,46.19 15.55,44.76 15.71,44.6
  Top 0.813: 15.71,45.87 15.71,44.6
N$192
  Top 0.305: 23.17,46.03 25.55,46.03 26.35,46.82 26.35,49.21 25.71,49.84 | 25.71,49.84 25.4,50 | 25.71,49.84 19.36,49.84 16.82,47.3 15.24,47.3 13.97,46.03
N$193  (via drill 3.2)
  other vias: 2.85,2.85
N$194
  Top 0.61: 13.01,38.25 11.11,38.25 10.95,38.41 10.95,42.06 10.16,42.86 1.11,42.86 0.79,43.17 0.79,54.6 1.11,54.92 4.6,54.92 4.92,54.6
N$195
  Top 0.61: 16.82,37.14 16.82,37.94 16.19,37.94 13.81,40.32 13.81,46.19 | 13.81,46.19 14.28,46.67 | 13.81,46.19 14.76,47.14 14.76,48.89 14.92,49.05 17.78,49.05 20.79,52.06 22.38,52.06 23.17,52.86 23.17,54.76 23.33,54.92 28.73,54.92 28.73,51.43 30.16,50 30.16,48.73 28.57,48.73 27.3,47.46 | 13.81,46.19 13.33,45.71 5.87,45.71 4.92,46.67 4.92,54.6
N$196
  Top 0.813: 16.66,37.62 15.71,37.62 14.6,38.73 | 14.6,38.73 | 14.6,38.73 13.49,39.84
N$197
  Top 1.016: 14.44,37.46 15.39,37.46
N$198
  Top 1.016: 14.44,37.62 | 14.44,37.62 12.7,39.36
N$199
  Top 1.016: 5.23,45.87 4.92,46.19
N$200
  Top 1.016: 10.79,42.86 11.11,42.54
N$201
  Top 1.27: 15.24,48.57 17.3,48.57
N$202
  Top 1.27: 16.66,47.94 15.24,47.94
N$203
  Top 0.406: 17.78,48.57 19.52,50.32 19.84,50.63
  Top 1.016: 19.52,50.32 21.74,50.32
N$204
  Top 1.016: 18.73,17.93 18.57,17.93 17.78,18.73 17.93,18.73 18.41,18.25
N$205
  Top 0.813: 18.41,18.41 | 17.93,18.88 18.41,18.41
N$207
  Top 0.813: 18.09,18.73 18.09,22.06
N$208
  Top 1.27: 13.81,7.61 15.87,7.61
N$209
  Top 1.27: 16.98,6.66 16.51,7.14
N$210
  Top 1.27: 13.81,6.66 16.51,6.66
N$211
  Top 1.016: 3.81,13.17 9.84,13.17
N$212
  Top 1.676: 12.85,3.33 19.52,3.33
N$213
  Top 1.016: 13.17,3.49 11.74,4.92 11.43,4.92 11.11,4.6 11.11,1.42 10.95,1.26 | 10.95,1.26 | 10.95,1.26 10.47,0.79 10,0.79 | 1.11,5.07 1.27,5.23 5.71,5.23 5.87,5.07 5.87,1.58 6.66,0.79 | 1.11,5.07 | 10,0.79 20.32,0.79 | 20.32,0.79 20.63,0.79 | 6.66,0.79 10,0.79 | 1.11,5.07 1.11,1.42 1.74,0.79 6.66,0.79 | 20.32,0.79 28.25,0.79 28.41,0.95 | 28.41,0.95 | 28.41,0.95 28.57,1.1 28.57,3.64 30,5.07
N$214
  Top 0.813: 22.06,9.36 22.06,9.2 23.33,7.93
N$215
  Top 1.422: 10.16,13.65 10.16,20
N$216
  Top 0.813: 11.43,21.74 10.47,20.79
N$217
  Top 1.27: 9.36,26.82 11.27,26.82
N$218
  Top 1.27: 29.52,4.92 33.49,4.92
N$219
  Top 1.422: 29.05,5.87 32.54,5.87 | 29.05,5.87 28.73,5.87 | 29.05,4.92 29.05,5.87
N$220
  Top 2.54: 20.47,1.9 20.47,3.17
N$221
  Top 1.422: 19.68,16.34 20.32,15.71
N$226
  Top 1.27: 29.52,31.9 29.52,31.11 30.48,31.11
N$227
  Top 1.27: 27.94,25.23 30.48,27.77
N$233
  Top 1.27: 28.73,27.77 30,27.77
N$234
  Top 1.676: 62.86,20.47 62.86,23.65
N$235  (via drill 0.9)
  other vias: 2.85,44.44
N$236  (via drill 0.9)
  other vias: 19.36,32.7
N$237
  Top 1.422: 61.11,49.68 61.11,49.37 | 61.11,49.68 61.11,50.16 61.91,50.16 64.61,47.46 64.61,43.81 61.75,43.81 61.59,43.97 61.27,44.13 61.59,43.81 61.11,44.28 61.11,49.68
N$238
  Top 1.422: 62.86,45.4 62.86,48.25
N$239
  Top 1.422: 20.47,51.11 20.79,51.43 23.49,51.43 23.65,51.59
N$240
  Top 1.422: 22.06,50.48 25.24,50.48
N$241
  Top 1.422: 23.65,52.06 23.65,54.29
N$242
  Top 1.422: 23.33,52.06 23.01,52.06
N$243
  Top 1.422: 26.35,45.87 26.67,46.19
N$244
  Top 1.422: 26.98,46.03 26.98,49.68 | 26.98,49.68 26.98,50.16 | 23.97,51.11 25.55,51.11 26.98,49.68
N$246
  Top 1.422: 63.65,47.3 63.65,46.03 63.5,45.87
N$247
  Top 0.813: 70.96,14.6 70.8,14.44 66.99,14.44 66.83,14.6 66.83,16.82
N$248
  Top 0.813: 66.99,16.98 70.8,16.98
N$249
  Top 0.813: 70.96,14.6 70.96,16.82 70.8,16.98
N$250
  Top 0.813: 73.18,15.39 74.93,15.39
N$251
  Top 0.813: 69.53,19.84 69.53,18.57 73.5,18.57 73.66,18.73 73.66,20 73.5,20.15 69.69,20.15 69.53,20
N$252
  Top 0.813: 65.24,6.82 65.24,8.73 65.4,8.88 70.48,8.88 70.64,8.73 70.64,6.98 70.48,6.82 65.24,6.82
N$253
  Top 1.016: 70.8,0.79 70.64,0.79 | 70.8,0.79 | 70.8,0.79 70.96,0.95 70.96,5.23 65.4,5.23 61.11,0.95
N$254
  Top 1.676: 62.7,1.58 64.92,1.58
N$255
  Top 1.676: 65.4,1.58 65.4,4.44
N$256
  Top 1.676: 63.34,2.22 64.92,3.8
N$257
  Top 0.813: 36.35,37.62 36.35,31.27 35.4,31.27 35.4,32.54 33.81,34.12 34.44,34.12 34.92,34.6 | 34.92,34.6 35.08,34.76 | 34.92,33.17 34.92,34.6
N$258
  Top 0.61: 27.94,23.49 28.41,23.49 | 27.94,23.49 25.55,23.49 24.28,22.22 29.05,22.22 29.05,23.49 27.94,23.49
N$259
  Top 0.61: 24.92,22.54 25.08,22.54 25.24,22.7
N$260
  Top 1.422: 75.72,29.68 75.56,29.68 75.56,32.7 78.74,32.7 78.74,30
N$261
  Top 1.422: 77.15,27.77 78.89,27.77 78.89,23.96 76.99,23.96 76.99,27.62
N$262
  Top 1.422: 78.58,30 76.35,30 75.88,29.52 75.56,29.52
N$263
  Top 1.422: 76.99,31.58 76.99,32.54
N$264
  Top 1.422: 70.48,45.08 70.48,41.74 70.32,41.59 66.99,41.59 66.83,41.74 66.83,45.24 66.99,45.4 70.32,45.4 70.48,45.24
N$265
  Top 0.813: 69.53,49.84 69.53,54.92 70.8,54.92 70.8,49.84 69.53,49.84
N$266
  Top 0.61: 60.48,42.22 64.92,42.22 64.92,40.79
N$267
  Top 0.813: 34.92,34.76 34.92,47.46
N$268
  Top 1.016: 32.06,48.25 32.06,47.14
N$269
  Top 0.61: 27.62,48.09 27.62,44.76 25.55,44.76
N$270
  Top 1.27: 29.21,49.21 27.78,49.21 27.78,48.73
N$271
  Top 0.813: 50.64,53.02 64.92,53.02 65.88,52.06 | 65.88,52.06 66.35,51.59 | 65.88,52.06 67.78,52.06 67.78,49.21 | 67.78,49.21 67.78,49.05 | 67.78,49.21 67.78,48.57 68.42,47.94
N$272
  Top 1.676: 37.14,39.36 40.48,39.36 42.22,37.62
N$273
  Top 1.27: 72.86,9.68 72.86,0.79 80.48,0.79 | 80.48,0.79 80.8,0.79 | 80.48,0.79 81.75,0.79 82.07,1.1 82.07,5.87 83.34,7.14 87.15,7.14 88.42,5.87
N$274
  Top 1.27: 79.05,10 79.05,9.2 77.31,7.46
N$275
  Top 1.27: 73.97,9.68 73.97,9.52 75.88,7.61
N$276
  Top 1.016: 78.42,12.54 78.42,14.92 76.35,16.98 | 76.35,16.98 | 76.35,16.98 75.56,17.77 75.56,20.79 74.45,21.9 69.85,21.9
N$277
  Top 1.016: 69.85,21.9 69.85,22.38 72.23,24.76 | 72.23,24.76 | 72.23,24.76 72.39,24.92 72.39,32.85
N$278
  Top 1.016: 75.08,22.22 75.08,26.98 73.66,28.41
N$279  (via drill 0.9)
  Top 1.422: 71.12,22.7 v73.5,22.7 73.66,22.7
N$280
  Top 1.422: 71.91,23.81 73.5,23.81
N$281
  Top 1.422: 74.13,24.12 74.13,27.14
N$282
  Top 1.422: 73.81,13.01 72.39,13.01 71.75,12.38
N$283
  Top 1.422: 72.86,10.15 72.86,11.11
N$284
  Top 1.422: 59.21,16.66 64.77,16.66 64.77,13.65 65.88,12.54
N$285
  Top 1.422: 62.38,11.58 72.07,11.58
N$286
  Top 1.422: 62.54,9.04 62.54,10.79
N$287
  Top 1.422: 62.7,10.63 63.5,10.63
N$288
  Top 1.778: 58.42,6.34 62.38,6.34
N$289
  Top 2.184: 58.42,5.07 60.96,5.07
N$290
  Top 2.184: 57.78,4.12 59.69,4.12 59.84,3.96
N$291
  Top 2.184: 61.27,5.71 61.27,9.2 61.59,9.52
N$292
  Top 2.184: 63.34,12.54 63.34,15.87
N$293
  Top 2.184: 68.42,38.57 66.99,38.57 66.83,38.41
N$294
  Top 2.184: 65.72,26.35 65.72,26.82
N$295
  Top 2.184: 42.38,5.23 42.38,3.64
N$296
  Top 2.184: 40.32,16.34 40.32,19.36
N$297
  Top 2.184: 38.73,17.93 38.73,19.52
N$298
  Top 0.813: 34.76,25.08 34.76,24.6 35.56,23.81
N$299
  Top 0.813: 34.76,25.23 34.76,26.35 35.08,26.66 41.27,26.66
N$300
  Top 1.676: 58.26,41.9 58.26,43.65
N$301
  Top 0.61: 24.44,43.65 24.44,44.13 24.92,44.6
N$302
  Top 1.676: 35.71,38.25 35.71,40
N$303
  Top 1.676: 58.42,52.54 58.42,52.06 58.57,51.91
N$304
  Top 1.422: 64.61,50.79 66.99,48.41 66.99,47.46 71.59,47.46
N$305
  Top 0.813: 66.83,48.09 70.64,48.09 | 70.64,48.09 70.8,48.09 | 70.64,48.09 71.27,48.09 72.23,49.05
N$306
  Top 1.27: 67.31,51.43 66.35,51.43 66.19,51.59
N$307
  Top 1.27: 64.29,52.54 65.88,50.95
N$308
  Top 1.27: 67.15,50 67.15,49.05
N$309
  Top 1.27: C33.2 75.4,36.35 IC2.4
N$310
  Top 1.27: C43.1 98.26,48.73 IC3.6
N$311
  Top 1.27: R18.2 85.08,40.96 85.24,40.79 C37.1 85.47,40.88 85.56,40.79 85.56,38.89 | RFC10.2 85.56,38.57 | 85.56,38.57 85.56,38.89 | 85.56,38.89 L5.1 | 85.56,38.57 IC2.1
N$312
  Top 1.27: C35.1 77.94,48.73 IC2.6
N$313
  Top 1.422: C52.2 89.69,10.95 88.42,10.95 | 88.42,10.95 RF_GAIN.2 | D12.A 88.53,11.06 88.42,10.95
N$314
  Top 1.27: C40.2 91.59,37.62 91.28,37.94 L6.2
N$315
  Top 1.27: C40.1 94.77,37.62 94.86,37.7 94.86,38.57 | 94.86,38.57 C41.1 | 94.86,38.57 94.77,38.57 | 94.86,38.57 IC3.4
N$316
  Top 1.27: IC2.5 75.4,47.78 C34.1 75.31,51.67 75.08,51.91 R19.1
N$317
  Top 1.016: R21.1 103.34,44.6
  Top 1.27: L7.2 108.97,45.78 C45.2 103.43,43.88 103.34,43.97 103.34,44.6 IC3.8 103.98,46.82 | C44.2 104.6,47.45 103.98,46.82 | 103.98,46.82 107.79,46.82
N$318
  Top 1.27: C47.2 103.43,34.67 103.34,34.76 103.34,35.08 | 103.34,35.08 IC3.1 R21.2 | 103.34,35.08 RFC11.2 | R21.2 105.4,40.96 105.56,40.79 | R21.2 103.34,41.11 | 105.56,40.79 C45.1 | 105.56,40.79 L7.1
N$319  (via drill 0.9)
  Top 0.254: 94.45,54.76 94.45,54.45 v93.82,54.45
  Top 1.27: R20.2 95.4,54.76 95.09,54.76 | 80.48,54.76 94.45,54.76 95.09,54.76 | 75.08,54.76 R19.2 | 80.48,54.76 C39.1 | 80.48,54.76 75.08,54.76 | R31.1 v88.42,15.39 | 95.09,54.76 96.04,54.76 96.04,54.13 74.45,54.13 74.45,54.76 75.08,54.76
  Bottom 0.254: v88.42,15.39 90.01,15.71 90.01,20.79 91.28,22.38 91.28,51.91 v93.82,54.45
N$320
  Top 1.27: C47.1 103.66,31.58 D10.A
N$321
  Top 0.61: 70.32,33.49 71.59,34.76 73.18,34.76 73.5,35.08 73.5,42.38 72.23,42.38 72.23,38.89 69.69,36.35 69.69,29.36 70.64,29.36 70.64,34.12
N$322
  Top 0.61: 74.77,35.08 74.77,39.52 75.08,39.84 75.72,39.84 76.04,39.52 76.04,35.08 75.72,34.76 75.08,34.76 74.77,35.08
N$323
  Top 1.016: 75.4,39.52 75.4,39.2
N$324
  Top 1.016: 75.4,35.08 75.4,35.39
N$325
  Top 1.422: 72.86,38.25 72.86,35.39 71.27,35.39 70.64,34.76
N$326
  Top 1.016: 72.54,32.85 73.5,32.85 73.5,28.73
N$327
  Top 1.27: D10.C R26.2 96.52,29.51 D9.C 98.67,27.37 C48.1 99.53,27.46 99.7,27.29 R22.2
N$328
  Top 1.27: IC3.5 95.72,47.78 C42.1 95.63,51.67 95.4,51.91 R20.1
N$330
  Top 1.27: R27.2 93.98,21.59 93.18,20.79 R23.1 93.5,20.79 R24.2
N$331
  Top 1.422: R24.1 93.65,15.88 94.77,14.76 R25.A
N$332
  Top 0.406: 90.64,25.87 IC5.3 | 90.64,25.87 93.82,25.87 | 93.82,25.87 95.09,25.87 | 93.82,25.87 94.45,26.5 | 93.82,25.87 94.45,25.23 | 90.64,25.87 90.32,26.19 90.32,25.55 90.64,25.87
  Top 0.61: 95.72,23.96 95.72,27.46 94.45,27.46 94.45,26.5 94.45,25.23 94.45,23.96
  Top 1.27: R27.1 95.09,25.87 R26.1
N$333
  Top 1.016: IC5.2 87.15,28.41 R28.2 | R28.2 | R29.2 R28.2
N$334
  Top 0.61: 80.8,25.87 IC5.6
  Top 1.016: IC5.6 R29.1
  Top 1.27: R29.1 D11.A
N$335
  Top 1.27: R30.2 84.61,20.15 D11.C 84.61,17.61 | D12.C 84.5,14.55 84.29,15.71 | 84.29,15.71 R31.2 | 84.46,15.23 84.61,15.23 | 84.46,15.23 R32.1 | 84.29,15.71 84.46,15.23 | 84.61,15.23 84.61,15.08 | 84.61,15.23 84.61,17.61 | 84.61,17.61 C50.+
N$336
  Top 1.27: 85.24,43.97 85.08,43.8 R18.1 IC2.8 84.28,47.45 C36.2 | 85.24,43.97 C37.2 | 85.24,43.97 L5.2
N$337
  Top 1.016: R33.1 82.39,10.63 | R33.1 R32.2 | R33.1 82.22,10.78 82.07,10.63 AGC_OUT.2 85.56,10.63 C51.1
N$338
  Top 1.422: Q1.1 115.6,38.06 115.41,38.25 | 115.41,38.25 L8.2 | C53.1 115.41,38.25
N$339
  Top 1.422: Q2.1 110.64,29.36 110.77,29.49 110.77,32.85 | 110.77,32.85 Q1.2 | 110.77,32.85 C54.1 110.96,32.85
N$340
  Top 1.27: Q2.2 115.6,27.01 115.41,26.82 | 115.41,26.82 C56.1 | C55.1 115.41,26.82
N$341
  Top 1.27: C56.2 115.41,23.65 IC4.1 111.6,23.65 R34.2
N$342
  Top 1.27: R36.2 114.77,16.03 IC4.4
N$343
  Top 1.27: R38.1 115.72,18.57 IC4.3
N$344
  Top 1.27: R38.2 115.72,21.42 115.41,21.11 IC4.2
N$345
  Top 0.813: 115.09,11.58 111.28,11.58 111.28,10.31 115.09,10.31
N$346
  Top 1.27: R35.2 108.9,6.02 107.79,7.14 107.79,7.77 107.47,8.09 107.63,8.26 R41.1 IC4.8 103.34,8.41 103.02,8.09 R44.1
N$347
  Top 1.27: R42.1 109.06,18.57 IC4.12 103.34,18.57 103.02,18.25 R43.1 102.86,18.1 102.71,18.25 102.07,17.61 C60.2
N$348
  Top 1.016: R44.2 103.02,10.95 C63.1
  Top 1.27: R44.2 103.02,11.58 104.93,13.49 IC4.10
N$349
  Top 1.27: R40.1 IC4.6 C58.1
N$350
  Top 1.016: C63.2 98.26,10.95 97.63,10.31 97.63,9.68 | BFO_IN.1 97.63,9.36 | 97.63,9.36 97.63,9.68 | 97.63,9.68 97.63,11.58 98.58,11.58 98.58,10.31 97.63,9.36
N$351
  Top 1.27: R39.1 IC4.5
N$352
  Top 0.813: 50.64,52.86 50.64,50.63 47.46,47.46 35.08,47.46
N$353
  Top 1.27: C62.1 102.71,25.87 102.39,26.19 AF_OUT.1
N$354
  Top 3.81: 49.05,46.19 51.27,48.41
N$355
  Top 0.813: 97.63,45.24 97.63,49.68 98.58,49.68 98.58,45.24 97.63,45.24
N$356
  Top 0.813: 94.77,52.22 94.77,45.24 96.04,45.24 96.04,52.54 94.77,52.54
N$357
  Top 0.813: 78.26,45.24 77.31,45.24 77.31,49.68 78.26,49.68 78.26,45.24
N$358
  Top 0.813: 75.72,52.22 75.72,45.24 75.08,45.24 74.45,45.87 74.45,52.22 75.72,52.22
N$359
  Top 1.422: 113.82,39.52 113.82,37.62 115.41,36.03
N$360
  Top 1.27: 82.7,45.24 82.7,46.19 | 82.7,45.24 82.7,43.33 87.47,43.33 87.47,47.78 87.15,48.09 83.97,48.09 82.7,46.82 82.7,45.24
N$361
  Top 1.27: 82.7,41.43 82.7,41.11 | 82.7,41.43 87.47,41.43 87.47,36.98 85.56,35.08 83.34,35.08 82.7,35.71 82.7,41.43
N$362
  Top 1.27: 83.34,36.03 85.88,36.03
N$363
  Top 0.61: 87.15,14.76 87.47,14.76 | 87.15,14.76 86.51,14.76 86.51,16.03 89.05,16.03 89.05,14.76 87.15,14.76
N$364
  Top 0.813: 81.12,45.55 81.12,45.87 | 81.12,45.55 81.12,43.33 79.21,43.33 | 81.12,45.55 81.12,48.09 83.02,50 88.42,50
N$365
  Top 1.27: 72.54,49.05 72.54,48.73 | 72.54,49.05 72.54,54.45 | 72.54,45.87 72.54,49.05
N$366
  Top 0.813: 78.26,42.38 78.26,37.62 77.62,37.62 77.62,41.11
N$367
  Top 0.813: 110.33,29.04 111.28,29.04 111.28,36.35 110.33,36.35 110.33,29.04
N$368
  Top 0.813: 116.04,29.68 116.04,26.19 113.18,26.19 113.18,27.77 115.09,29.68 116.04,29.68
N$369
  Top 1.422: 114.14,27.46 115.41,28.73
N$370
  Top 0.61: 102.71,41.11 102.71,40.79 | 102.71,41.11 102.71,41.74 109.06,41.74 109.37,41.43 109.37,40.48 109.06,40.16 106.83,40.16 105.56,38.89 105.56,34.12 105.25,33.81 103.02,33.81 102.71,34.12 102.71,41.11
N$371
  Top 0.61: 106.52,41.43 109.06,41.43
N$372
  Top 1.016: 104.93,39.2 106.2,40.48
N$373
  Top 0.813: 90.96,36.98 92.23,36.98 92.23,39.2 90.96,39.2 90.96,36.98
N$374
  Top 1.422: 95.72,41.11 95.72,37.3 94.13,37.3 94.13,41.11 95.4,41.11
N$375
  Top 1.016: 99.53,32.22 104.61,32.22 104.61,30.95 99.53,30.95 99.53,32.22
N$376
  Top 0.61: 94.13,34.12 92.86,32.85 92.86,27.77
N$377
  Top 1.016: 95.09,16.34 93.18,16.34 93.18,15.39 94.45,14.12 94.45,12.85 94.77,12.85 95.09,13.17 95.09,16.34
N$378
  Top 0.813: 94.45,29.04 96.36,29.04 97.31,28.09 97.31,26.5 100.17,26.5 100.17,27.77 95.72,32.22 94.77,32.22 94.45,31.9 94.45,29.04
N$379
  Top 1.016: 99.21,27.77 95.72,31.27
N$380
  Top 1.016: 95.72,30.63 96.36,30
N$381
  Top 0.813: 93.18,34.12 100.8,34.12 101.44,34.76 101.44,41.43 100.17,41.43 100.17,36.03
N$382
  Top 0.813: 93.18,33.49 93.18,34.44
N$383
  Top 1.016: 100.17,34.44 101.12,35.39
N$384
  Top 0.406: 101.75,25.23 101.75,28.09 103.02,28.09 103.02,27.14 103.66,26.5 103.66,25.23 101.75,25.23
N$385
  Top 0.61: 103.34,26.5 103.02,26.82
N$386
  Top 0.406: 103.66,23.33 103.66,20.15 100.17,20.15 100.17,21.74 101.75,23.33 103.02,23.33
N$387
  Top 0.813: 103.34,21.42 103.34,22.06
N$388
  Top 0.813: 102.07,22.7 101.75,22.7 101.12,22.06
N$389
  Top 0.813: 101.75,20.47 101.75,22.06
N$390
  Top 1.422: 118.58,30.63 117.63,31.58
N$391
  Top 0.305: 110.33,22.38 111.6,22.38 112.23,23.01 116.36,23.01 116.36,24.6 116.04,24.92 111.6,24.92 110.33,23.65 110.33,22.38
N$392
  Top 0.61: 111.6,24.6 116.04,24.6
N$393
  Top 0.61: 115.09,24.28 111.28,24.28 110.64,23.65
N$394
  Top 0.61: 111.91,23.33 111.91,23.01 111.6,22.7
N$395
  Top 0.61: 110.01,27.46 109.69,27.46 108.74,28.41
  Top 0.813: 108.74,28.41 108.74,36.98 109.69,37.94
N$396
  Top 0.61: 110.33,37.62 108.74,37.62 108.42,37.3
N$397
  Top 0.813: 106.83,23.01 106.83,21.11
N$398
  Top 0.813: 107.15,22.7 108.1,22.7
N$399
  Top 0.813: 106.52,20.79 105.25,20.79 104.93,21.11 104.93,24.28 105.25,24.6
N$400
  Top 0.813: 105.25,24.92 105.25,26.82 104.93,27.14
N$401
  Top 0.813: 104.93,29.04 107.15,29.04
N$402
  Top 0.813: 107.15,28.41 107.15,29.04 107.15,30 | 107.15,28.41 107.15,28.09 | 107.15,28.41 104.61,28.41
  Top 1.27: 109.69,26.5 109.37,26.5 108.1,25.23
  Top 1.422: 109.69,26.5 107.15,29.04
N$403
  Top 0.813: 104.61,27.77 104.61,28.73
N$404
  Top 0.813: 109.06,24.6 109.06,23.65
N$405
  Top 1.27: 108.42,24.28 110.64,26.5
N$406
  Top 1.27: 107.79,23.96 107.79,26.19
N$407  (via drill 0.9)
  other vias: 15.08,24.92
N$408
  Top 0.254: 111.6,17.93 111.6,21.74 108.1,21.74 108.1,20.47 110.96,20.47 | 111.6,17.93 111.6,17.61 111.91,17.3 | 111.6,17.93 111.28,17.61 | 116.04,17.3 116.36,16.98 116.36,14.76 115.72,14.12 115.72,12.85 116.36,12.22 | 111.28,21.11 109.37,21.11
  Top 0.305: R36.1 117.31,16.35 116.99,16.66 116.68,16.98 116.36,17.3 116.04,17.3 | 116.04,17.3 111.91,17.3 | 111.91,17.3 111.6,17.3 111.28,17.61 111.28,17.93 | 111.91,17.3 111.28,17.3 110.96,17.61 110.96,20.15 | 110.96,20.15 110.64,20.47 | 110.96,20.15 110.96,20.47 | 116.04,17.3 116.68,17.3 117.63,16.34 117.63,15.08 116.68,14.12
  Top 0.406: 116.04,6.82 115.72,6.5 111.6,6.5 111.6,5.87 R35.1 | 116.04,6.82 116.36,7.14 C57.2 116.36,14.44 116.68,14.76 | 116.68,14.76 116.99,15.08 R36.1 | 116.68,16.98 116.68,16.34 | 116.99,16.66 116.99,16.34 | 116.68,14.76 116.68,15.08 | 116.04,6.82 114.14,4.92 111.6,4.92 111.28,5.23
  Top 0.61: 111.28,17.93 111.28,21.11
  Top 0.813: 116.68,14.76 116.68,12.85 116.36,12.54 116.04,12.85
  Top 1.016: R34.1 R37.2
  Top 1.27: R34.1 110.01,21.11 109.37,21.11
N$409
  Top 0.813: 109.37,20.79 110.64,20.79
N$410
  Top 0.813: 115.09,18.25 115.41,18.25 | 115.09,18.25 112.55,18.25 112.55,19.2 116.36,19.2 116.36,18.25 115.09,18.25
N$411
  Top 0.813: 112.55,20.79 116.36,20.79 116.36,22.06 115.09,22.06 114.45,21.42 112.55,21.42 112.55,20.79
N$412
  Top 0.305: 114.77,16.34 115.09,16.34 115.41,15.08 113.5,15.08 113.18,15.39
  Top 0.813: 113.82,15.39 113.5,15.71 112.23,15.71 112.23,16.34 114.77,16.34
N$413
  Top 0.813: 113.82,13.81 114.14,13.81 | 113.82,13.81 112.87,13.81 112.55,14.12 110.96,14.12 110.96,12.85 114.45,12.85 114.45,13.81 113.82,13.81
N$414
  Top 0.406: 114.14,15.39 114.45,15.39
N$415
  Top 0.406: 116.68,14.44 117.31,15.08 | 116.68,14.44 116.36,14.12 | 116.68,14.44 116.36,14.44 116.04,14.12
N$416
  Top 0.813: 101.75,18.88 100.48,18.88 100.48,16.66 102.39,16.66 103.66,17.93 109.69,17.93 109.69,18.88 101.75,18.88 | 101.75,18.88 101.75,17.93
N$417
  Top 0.254: 83.97,27.14 83.97,28.41 84.61,29.04 90.32,29.04 90.64,28.73 90.64,28.09 89.69,27.14 83.97,27.14
N$418
  Top 1.016: 87.78,10.63 90.32,10.63 90.32,11.9 89.05,13.17 87.78,13.17 87.78,10.63
N$419
  Top 0.406: 118.58,14.44 118.26,14.12
N$420
  Top 0.406: 117.95,12.54 117.31,11.9 117.31,5.55
N$421
  Top 0.61: 114.77,5.87 114.45,5.87 | 114.77,5.87 115.09,6.18 | 114.14,5.23 114.77,5.87
  Top 1.016: 114.45,5.87 114.45,6.18
N$422
  Top 0.406: 104.29,13.49 104.93,14.12 106.83,14.12 107.15,13.81 107.15,13.17 106.52,12.54 104.61,12.54
N$424
  Top 0.813: 103.66,11.58 103.66,10.31 100.48,10.31 100.48,11.58 102.71,11.58
N$425
  Top 0.813: 106.83,13.81 106.52,13.81
N$426
  Top 0.813: 106.2,13.17 106.83,13.17
N$427
  Top 0.813: 105.25,12.85 106.52,12.85
N$428
  Top 0.61: 109.37,5.23 108.1,5.23 108.1,5.87 106.52,7.46 102.39,7.46 102.39,9.04 108.1,9.04
N$429
  Top 0.61: 103.66,7.77 106.52,7.77 107.15,7.14
N$430
  Top 1.016: 113.18,1.74 117.63,6.18
N$431
  Top 1.676: 117.95,1.42 117.95,4.92
N$432
  Top 1.676: 114.77,1.42 117.63,4.28
N$433
  Top 0.61: 84.61,28.73 86.83,28.73
N$434
  Top 1.676: 111.91,2.38 115.09,2.38
N$435
  Top 0.61: 85.88,28.41 84.29,28.41
N$436
  Top 0.61: 90.32,28.73 89.37,28.73
N$437
  Top 0.61: 90.32,28.09 90.32,28.41
N$438
  Top 0.61: 90.01,28.41 90.01,27.77 89.69,27.46 87.15,27.46
N$439
  Top 0.61: 87.15,27.77 89.69,27.77
N$440
  Top 0.254: 85.24,26.5 85.24,24.6 85.56,24.28 85.56,22.7 83.66,22.7 83.66,24.28 83.02,24.92 81.12,24.92 80.48,25.55 80.48,26.19 80.8,26.5 85.24,26.5
N$441
  Top 0.61: 85.24,24.28 85.24,23.96
N$442
  Top 0.61: 80.8,26.19 81.43,26.19
N$443
  Top 0.61: 80.8,25.55 81.43,25.55
N$444
  Top 0.61: 81.12,25.23 83.34,25.23 83.97,25.23
  Top 1.016: 83.34,25.23 83.97,24.6
N$445
  Top 0.254: 87.15,24.92 87.15,26.5 85.88,26.5 85.88,25.23 86.51,24.6
N$446
  Top 1.016: 89.69,11.58 88.74,12.54
N$447
  Top 0.406: 90.96,23.96 91.28,24.28
N$448
  Top 0.813: 83.02,11.58 83.66,10.95 86.2,10.95 86.2,10 85.88,9.68 81.75,9.68 81.75,12.85 83.02,12.85 83.02,11.58
N$449
  Top 1.016: 84.93,30.63 84.93,32.54
N$450
  Top 1.422: 88.1,33.49 91.59,33.49 91.91,33.17
N$451
  Top 1.422: 89.05,34.44 91.91,34.44
N$452
  Top 1.422: 85.24,32.54 87.15,32.54
N$453
  Top 1.422: 85.24,30.95 86.2,31.9
N$454
  Top 0.61: 88.1,22.38 88.74,23.01
N$455
  Top 0.305: 86.51,8.41 87.15,9.04 90.64,9.04 90.64,7.46 90.01,6.82
  Top 0.406: 90.01,6.82 90.01,3.01 89.69,2.69 88.74,2.69 88.1,3.33 88.1,5.87
N$456
  Top 0.813: 94.45,19.84 95.72,21.11 95.72,22.06 94.13,22.06
N$457
  Top 0.61: 92.86,18.25 92.86,20.79
N$458
  Top 0.813: 94.13,20.47 94.77,21.11
N$459  (via drill 0.9)
  Top 0.254: 110.33,4.6 109.69,3.96
  Top 0.406: R41.2 110.48,7.92 110.33,7.77 110.33,7.46 110.33,7.14 | 110.33,3.96 110.33,4.6 110.33,7.14 | 109.69,3.64 110.33,3.96 | 110.01,9.04 108.74,10.31 | 110.33,7.14 110.96,7.77 | 110.33,3.96 110.33,3.64 110.01,3.33
  Top 0.61: 91.59,27.77 91.59,32.22 90.96,32.85 88.1,32.85 85.56,30.31 83.97,30.31 | R41.2 110.48,8.89 110.33,9.04 109.37,10 109.06,10.31 109.06,10.63 108.74,10.95 R40.2
  Top 0.813: 115.09,7.77 110.96,7.77 110.01,7.77 | 110.01,7.77 110.01,9.04 | IC5.7 82.07,28.41 82.39,28.73 | 82.7,29.04 83.97,30.31 84.29,30.63 84.29,32.22 84.29,33.17 | 82.7,29.04 82.39,28.73 | 103.34,4.6 103.02,4.28 103.02,3.33 | 103.02,3.33 103.02,0.79 102.71,0.47 101.75,0.47 | 93.18,0.47 92.55,0.47 92.23,1.1 C65.+ 91.91,0.79 | 93.18,0.47 101.75,0.47 | 80.8,34.44 80.8,39.84 81.12,40.16 81.12,41.43 79.85,41.43 79.85,40.16 | 79.85,40.16 80.16,40.16 80.16,36.66 79.53,36.03 79.21,36.03 | 79.21,36.03 77.62,36.03 77.62,34.76 80.16,34.76 | 79.85,40.16 79.85,36.66 79.21,36.03 | 99.21,35.39 88.74,35.39 86.51,33.17 | 109.06,10.31 108.74,10.31 108.42,10.31 108.42,16.03 110.01,16.03 110.01,15.08 109.37,14.44 109.37,10 | 110.33,9.04 115.09,9.04 | 110.01,7.77 110.33,7.46 110.96,8.09 | 110.01,3.96 109.69,3.96 107.47,3.96 | 101.75,0.47 102.07,0.47 102.71,1.1 102.71,5.23 | 102.71,5.23 106.2,5.23 105.88,5.55 102.71,5.55 102.71,5.23 | 106.52,4.28 103.98,4.28 103.02,3.33 | 93.18,0.47 84.29,0.47 84.29,4.6 84.93,5.23 85.88,5.23 86.2,4.92 86.2,2.38 87.78,0.79 | 82.7,29.04 82.7,28.09 80.8,28.09 80.8,28.73 82.39,28.73 | 93.18,0.47 92.23,1.42 | 101.12,36.98 100.48,36.98 98.58,35.08
  Top 1.016: 91.91,6.5 91.59,6.18 91.59,1.74 90.64,0.79 | 91.28,14.44 91.28,21.42 90.01,21.42 90.01,19.84 90.64,19.2 90.64,14.12 92.23,12.54 | 84.29,32.22 83.34,33.17
  Top 1.27: C38.1 IC2.2 80.48,35.39 80.16,35.08 | 80.16,35.08 RFC10.1 | 82.7,33.17 83.34,33.17 84.29,33.17 86.51,33.17 87.15,33.17 89.05,35.08 92.23,35.08 | 82.7,33.17 82.07,33.17 80.8,34.44 80.16,35.08 | 92.23,35.08 RFC11.1 98.58,35.08 99.53,35.08 100.8,36.35 IC3.2 C46.1 | 92.23,35.08 v92.23,29.36 C49.1 | R41.2 C59.1 | R42.2 109.06,15.39 108.9,15.24 R39.2 108.74,13.49 108.9,13.32 R40.2 | 109.69,3.64 107.47,3.64 106.2,4.92 C66.+ 103.66,4.92 103.34,4.6 | +-5V1.P$2 85.09,0.94 85.24,0.79 87.78,0.79 90.64,0.79 91.91,0.79 | 92.23,12.54 92.23,12.85 v91.59,13.49 90.96,14.12 90.96,14.44 | 90.96,14.44 C64.+ 90.96,20.15 90.32,20.79 R23.2 | 92.23,1.1 92.23,1.42 92.23,12.54 | 92.23,12.54 92.23,13.17 90.96,14.44 | 82.7,33.17 81.43,33.17 79.53,35.08
  Bottom 0.305: v92.23,29.36 92.23,14.12 v91.59,13.49
N$460
  Top 1.422: 84.93,4.28 85.56,4.28 85.56,1.74 86.2,1.1
N$461
  Top 0.61: 88.42,8.73 87.15,8.73
N$462
  Top 0.61: 89.69,6.82 90.32,7.46
N$463
  Top 0.813: 89.69,3.01 89.05,3.01 88.74,3.33
N$464
  Top 1.016: 88.74,3.64 88.74,5.55
N$465
  Top 1.016: 88.74,6.5 88.74,7.46
N$466
  Top 1.016: 88.1,7.14 88.74,7.77
N$467
  Top 0.254: 85.24,19.52 85.24,14.44 85.88,13.81 85.88,11.9 84.61,11.9 84.29,12.22 84.29,13.17 83.34,14.12 81.75,14.12 81.43,14.44 81.43,16.03 82.07,16.03 83.02,16.98
N$468
  Top 0.61: 85.56,13.81 85.24,14.12 85.24,20.79 81.75,20.79 81.75,19.52 82.39,19.52 83.34,18.57
N$469
  Top 1.016: 81.43,17.93 81.43,17.61 | 81.43,17.93 80.8,17.93 80.16,18.57 | 81.43,17.93 81.43,17.3 80.8,17.3 79.85,16.34
N$470
  Top 0.61: 83.34,14.44 81.75,14.44 | 83.34,14.44 83.97,14.44 | 84.61,12.22 84.61,13.17 83.34,14.44
N$471
  Top 1.016: 83.34,16.66 83.34,19.2 | 83.34,16.66 83.34,16.03 | 82.39,15.71 83.34,16.66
